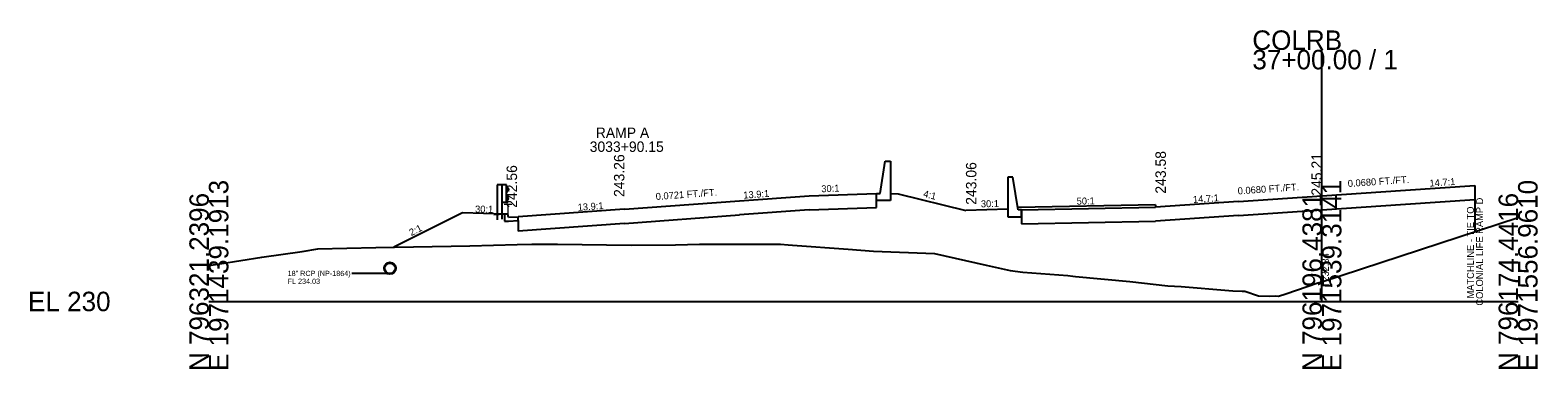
# Model space of a CAD drawing. Extents: x -26 to 1971766, y -10 to 796432.
# Drawn here: x -25.7 to 191, y 1490.3 to 1539 of the extents above; entities that cross this region are included whole.
import ezdxf

# ---------------------------------------------------------------- set-up
doc = ezdxf.new("R2010")
doc.units = 0
for name, color, linetype in [('BR_AUTO DIMENSION', 7, 'Continuous'), ('BR_BORDER LINES', 7, 'Continuous'), ('BR_CENTER LINES', 7, 'Continuous'), ('BR_CONCRETE', 7, 'Continuous'), ('BR_DETAILS', 7, 'Continuous'), ('BR_PRESTRESSED BEAM', 7, 'Continuous'), ('BR_REBAR', 7, 'Continuous'), ('Default', 7, 'Continuous'), ('North Arrow', 7, 'Continuous'), ('RD_EX_Conc', 7, 'Continuous'), ('RD_EX_Road', 7, 'Continuous'), ('RD_HC_CL', 7, 'Continuous'), ('RD_HC_CL_Rel', 7, 'Continuous'), ('RD_PD_ALT1_TrvlWay', 7, 'Continuous'), ('RD_PD_Final_LnLine', 7, 'Continuous'), ('RD_PD_FOC', 7, 'Continuous'), ('RD_PD_GR', 7, 'Continuous'), ('RD_PD_MedBWall', 7, 'Continuous'), ('RD_PD_WallFill', 7, 'Continuous'), ('RD_SHT_IplotShp', 7, 'Continuous')]:
    doc.layers.add(name, color=color, linetype=linetype)

msp = doc.modelspace()

# ---------------------------------------------------------------- linework, layer by layer
at = {"layer": 'BR_AUTO DIMENSION'}
for p, q in [((160, 1500), (160, 1536.18)), ((0, 1500), (160, 1500)), ((160, 1500), (188.2, 1500))]:
    msp.add_line(p, q, dxfattribs=at)
at = {"layer": 'BR_BORDER LINES'}
msp.add_lwpolyline([(0, 1505.18), (1.59, 1505.43), (7.59, 1506.36), (13.4, 1507.2), (15.64, 1507.57), (24, 1507.75), (37.51, 1507.99), (44.32, 1508.2), (46.42, 1508.23), (47.73, 1508.22), (50.09, 1508.25), (60.71, 1508.1), (67.08, 1508.15), (70.51, 1508.25), (75.54, 1508.24), (82.19, 1508.22), (83.26, 1508.14), (83.89, 1508.1), (91.88, 1507.5), (95.54, 1507.23), (104.3, 1506.92), (111.74, 1505.2), (115.17, 1504.43), (117, 1504.22), (123.49, 1503.71), (124.2, 1503.62), (124.57, 1503.59), (132.41, 1502.85), (137.87, 1502.25), (139.78, 1502.14), (146.61, 1501.57), (147.21, 1501.55), (148.55, 1501.46), (148.93, 1501.49), (150.89, 1500.83), (152.42, 1500.76), (153.28, 1500.8), (153.75, 1500.75), (154.83, 1501.11), (159.42, 1502.66), (160, 1502.84), (188.2, 1512.06)], dxfattribs=at)
at = {"layer": 'BR_CENTER LINES'}
for q in [(36.48, 1512.76), (40.97, 1512.44)]:
    msp.add_line((42.48, 1512.56), q, dxfattribs=at)
at = {"layer": 'BR_DETAILS'}
for q in [(116.28, 1513.52), (136.07, 1513.58)]:
    msp.add_line((136.07, 1513.91), q, dxfattribs=at)
at = {"layer": 'BR_PRESTRESSED BEAM'}
for p, q in [((42.48, 1512.56), (42.48, 1511.56)), ((42.48, 1512.56), (42.48, 1511.56)), ((42.48, 1511.56), (43.06, 1511.56)), ((43.06, 1511.56), (44.48, 1511.64))]:
    msp.add_line(p, q, dxfattribs=at)
at = {"layer": 'North Arrow'}
for p, q in [((148, 1514.39), (160, 1515.21)), ((160, 1515.21), (172, 1516.02)), ((59.73, 1513.26), (76.29, 1514.49))]:
    msp.add_line(p, q, dxfattribs=at)
at = {"layer": 'RD_EX_Conc'}
for p, q in [((116.83, 1513.19), (116.83, 1513.17)), ((42.98, 1512.56), (42.48, 1512.56)), ((42.98, 1512.56), (42.48, 1512.56)), ((43.06, 1512.06), (42.98, 1512.56)), ((43.06, 1512.06), (42.98, 1512.56)), ((44.48, 1512.14), (43.06, 1512.06)), ((44.48, 1512.16), (44.48, 1512.14))]:
    msp.add_line(p, q, dxfattribs=at)
at = {"layer": 'RD_EX_Road'}
for p, q in [((95.99, 1513.5), (95.99, 1515.54)), ((182, 1516.7), (182, 1510.03)), ((86.29, 1513.17), (76.29, 1512.45)), ((86.29, 1513.17), (95.99, 1513.5)), ((116.83, 1513.19), (116.83, 1511.15)), ((116.83, 1513.17), (116.83, 1513.19)), ((116.83, 1512.67), (116.83, 1513.17)), ((148, 1512.35), (160, 1513.17)), ((160, 1513.17), (172, 1513.98)), ((172, 1513.98), (182, 1514.66)), ((44.48, 1512.14), (44.48, 1512.16)), ((44.48, 1511.64), (44.48, 1512.14)), ((44.48, 1511.64), (44.48, 1510.12)), ((59.73, 1511.22), (44.48, 1510.12)), ((59.73, 1511.22), (76.29, 1512.45)), ((116.83, 1511.15), (136.07, 1511.54)), ((148, 1512.35), (136.07, 1511.54))]:
    msp.add_line(p, q, dxfattribs=at)
at = {"layer": 'RD_HC_CL'}
for p, q in [((42.12, 1516.78), (41.46, 1516.78)), ((41.46, 1516.78), (41.46, 1511.73)), ((42.79, 1516.78), (42.12, 1516.78)), ((42.12, 1516.78), (42.12, 1511.84)), ((42.79, 1514.21), (42.79, 1516.78)), ((42.79, 1516.62), (43.06, 1516.18)), ((43.06, 1516.07), (42.79, 1515.63)), ((43.06, 1514.92), (42.79, 1515.36)), ((43.06, 1516.18), (43.06, 1516.07)), ((42.79, 1514.21), (42.12, 1514.21)), ((42.79, 1514.37), (43.06, 1514.81)), ((43.06, 1514.81), (43.06, 1514.92))]:
    msp.add_line(p, q, dxfattribs=at)
at = {"layer": 'RD_PD_Final_LnLine'}
for p, q in [((97.99, 1515.54), (99.08, 1515.5)), ((99.08, 1515.5), (108.83, 1513.06)), ((114.83, 1513.26), (108.83, 1513.06)), ((36.48, 1512.76), (26.57, 1507.8))]:
    msp.add_line(p, q, dxfattribs=at)
at = {"layer": 'RD_PD_FOC'}
msp.add_line((25.53, 1504.03), (20.53, 1504.03), dxfattribs=at)
for radius in [0.85, 0.75]:
    msp.add_circle((26.03, 1504.78), radius, dxfattribs=at)
at = {"layer": 'RD_PD_GR'}
for p, q in [((96.49, 1515.54), (97.24, 1520.2)), ((97.24, 1520.2), (97.99, 1520.2)), ((97.99, 1520.2), (97.99, 1514.54)), ((115.58, 1517.86), (114.83, 1517.86)), ((114.83, 1517.86), (114.83, 1512.19)), ((116.33, 1513.19), (115.58, 1517.86)), ((95.99, 1514.54), (95.99, 1515.54)), ((95.99, 1515.54), (96.49, 1515.54)), ((97.99, 1514.54), (95.99, 1514.54)), ((116.83, 1513.19), (116.33, 1513.19)), ((116.83, 1512.19), (116.83, 1513.19)), ((114.83, 1512.19), (116.83, 1512.19))]:
    msp.add_line(p, q, dxfattribs=at)
at = {"layer": 'RD_PD_MedBWall'}
for p, q in [((76.29, 1514.49), (86.29, 1515.21)), ((86.29, 1515.21), (95.99, 1515.54)), ((172, 1516.02), (182, 1516.7)), ((59.73, 1513.26), (44.48, 1512.16)), ((116.83, 1513.19), (136.07, 1513.58)), ((148, 1514.39), (136.07, 1513.58))]:
    msp.add_line(p, q, dxfattribs=at)

# ---------------------------------------------------------------- texts
at = {"layer": 'BR_AUTO DIMENSION'}
for s, p in [('COLRB', (150, 1536.18)), ('37+00.00 / 1', (150, 1533.38)), ('EL 230', (-26, 1498.6))]:
    msp.add_text(s, height=2.8, dxfattribs=at).set_placement(p)
for s, p in [('E 1971439.1913', (2.8, 1490)), ('E 1971539.3141', (162.8, 1490)), ('E 1971556.9610', (191, 1490)), ('N 796321.2396', (0, 1490)), ('N 796196.4381', (160, 1490)), ('N 796174.4416', (188.2, 1490))]:
    msp.add_text(s, height=2.8, rotation=90, dxfattribs=at).set_placement(p)
at = {"layer": 'BR_CONCRETE'}
for s, rotation, p in [('0.0680 FT./FT.', 3.8901, (163.75, 1516.46)), ('0.0721 FT./FT.', 4.126, (64.27, 1514.59)), ('13.9:1', 4.126, (76.86, 1514.78)), ('30:1', 2.3185, (88.06, 1515.7)), ('4:1', 345.9638, (102.62, 1515.06)), ('0.0680 FT./FT.', 3.8901, (147.93, 1515.39)), ('30:1', 359.1385, (38.26, 1512.79)), ('30:1', 0.8615, (110.98, 1513.54)), ('2:1', 26.5651, (29.1, 1509.39))]:
    msp.add_text(s, height=1, rotation=rotation, dxfattribs=at).set_placement(p)
at = {"layer": 'BR_REBAR'}
msp.add_text('LT', height=1.5, dxfattribs=at).set_placement((41.28, 1512.56))
at = {"layer": 'Default'}
for s, p in [('243.58', (137.57, 1515.5)), ('242.56', (44.3, 1513.47)), ('243.06', (110.33, 1513.9))]:
    msp.add_text(s, height=1.5, rotation=90, dxfattribs=at).set_placement(p)
at = {"layer": 'RD_HC_CL_Rel'}
for s, p in [('243.26', (59.73, 1515.03)), ('245.21', (160, 1515.21))]:
    msp.add_text(s, height=1.5, rotation=90, dxfattribs=at).set_placement(p)
at = {"layer": 'RD_PD_ALT1_TrvlWay'}
for s, rotation, p in [('14.7:1', 3.8901, (175.5, 1516.51)), ('50:1', 1.1458, (124.75, 1513.92)), ('14.7:1', 3.8901, (141.5, 1514.16)), ('13.9:1', 4.1113, (53.05, 1513.03)), ('MATCHLINE - TIE TO', 90, (181.85, 1500.43)), ('COLONIAL LIFE RAMP D', 90, (183.16, 1499.4))]:
    msp.add_text(s, height=1, rotation=rotation, dxfattribs=at).set_placement(p)
at = {"layer": 'RD_PD_FOC'}
for s, p in [('18" RCP (NP-1864)', (11.32, 1503.66)), ('FL 234.03', (11.32, 1502.53))]:
    msp.add_text(s, height=0.75, dxfattribs=at).set_placement(p)
at = {"layer": 'RD_PD_WallFill'}
for s, p in [('RAMP A', (55.61, 1523.51)), ('3033+90.15', (54.74, 1521.51))]:
    msp.add_text(s, height=1.5, dxfattribs=at).set_placement(p)
at = {"layer": 'RD_SHT_IplotShp'}
msp.add_text('232.84', height=1, rotation=90, dxfattribs=at).set_placement((161, 1502.84))

doc.saveas('drawing.dxf')
